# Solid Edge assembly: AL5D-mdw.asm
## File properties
Author: nakano
Template: Iso Metric Assembly.asm
Last saved by: nakano
Revision: 39
Application: Solid Edge
Username: nakano
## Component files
wgripper.asm
wrist.asm
Base.asm
waist.asm
shoulder.asm
elbow.asm
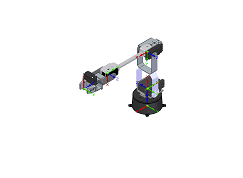
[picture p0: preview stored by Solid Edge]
